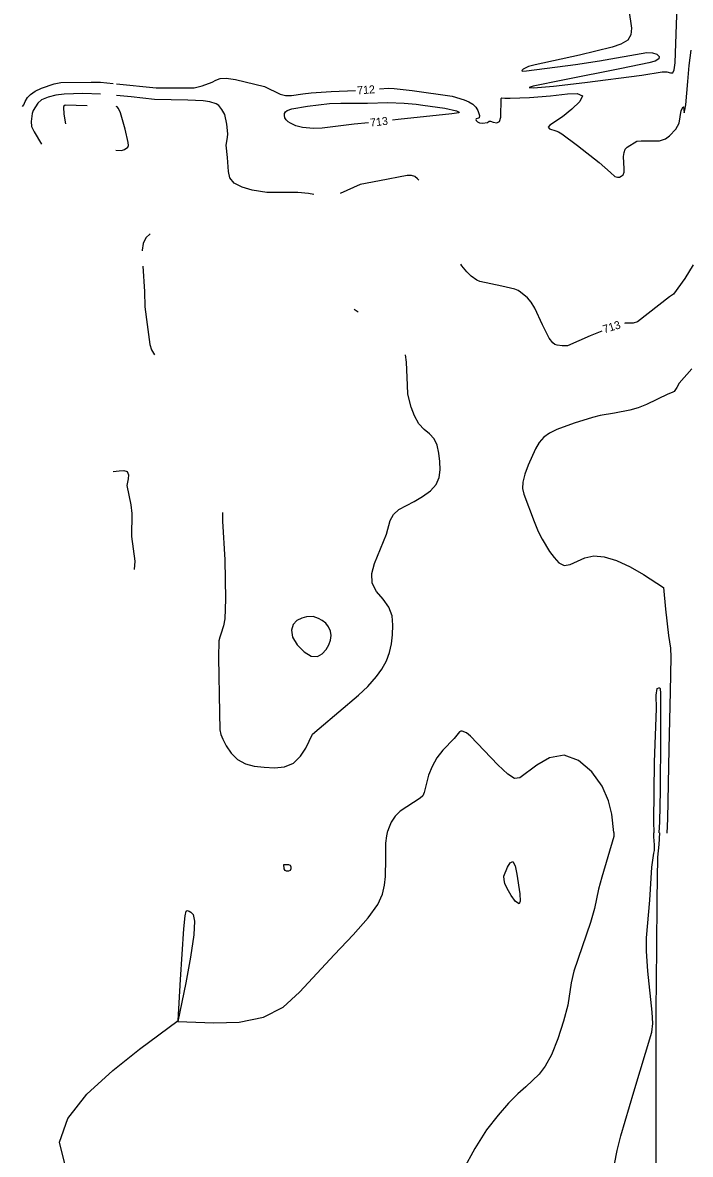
# Model space of a CAD drawing. Extents: x -468548933 to 3387700, y -306089263 to 1207014.
# Drawn here: x 1840205 to 1840538, y 537416 to 537981 of the extents above; entities that cross this region are included whole.
import ezdxf

# ---------------------------------------------------------------- set-up
doc = ezdxf.new("R2010")
doc.units = 0
doc.layers.add('DT_X_Contour_Minor', color=7, linetype='Continuous')
doc.layers.add('Level 19', color=7, linetype='Continuous')

msp = doc.modelspace()

# ---------------------------------------------------------------- linework, layer by layer
at = {"layer": 'DT_X_Contour_Minor'}
for points in [[(1840507.63, 537987.64), (1840508.91, 537978.47), (1840508.66, 537975.16), (1840507.03, 537972.57), (1840503.67, 537970.6), (1840499.31, 537969.11), (1840482.9, 537965.06), (1840460.77, 537960.16), (1840457.44, 537959.34), (1840454.78, 537957.98), (1840454.11, 537957.39), (1840454.34, 537957.09), (1840456.45, 537957.14), (1840481.01, 537960.37), (1840492.9, 537962.2), (1840516.67, 537966.34), (1840519.43, 537966.22), (1840521.6, 537965.49), (1840522.83, 537964.37), (1840522.65, 537963.15), (1840520.77, 537962.08), (1840517.52, 537961.14), (1840503.98, 537958.42), (1840474.59, 537952.57), (1840459.84, 537949.58), (1840457.79, 537948.88), (1840459.96, 537948.79), (1840469.92, 537949.59), (1840485.62, 537951.44), (1840514.13, 537954.97), (1840524.17, 537956.66), (1840526.6, 537956.67), (1840528.35, 537956.26), (1840529.53, 537956.26), (1840530.26, 537957.7), (1840530.69, 537961.18), (1840531.39, 537980.28), (1840532.25, 538003.02)], [(1840383.06, 537948.2), (1840387.5, 537948.52), (1840390.45, 537948.44), (1840399.41, 537947.42), (1840419.36, 537944.52), (1840425.33, 537942.72), (1840427.64, 537941.76), (1840429.68, 537940.52), (1840431.21, 537939), (1840432.23, 537937.39), (1840433.01, 537934.9), (1840432.83, 537933.79), (1840432.47, 537933.48), (1840431.33, 537933.21), (1840431.16, 537932.88), (1840431.38, 537932.35), (1840432.03, 537931.75), (1840433.09, 537931.27), (1840434.52, 537931.04), (1840437.05, 537931.35), (1840437.8, 537932.11), (1840438.46, 537932.05), (1840439.87, 537931.51), (1840441.6, 537931.14), (1840443, 537931.81), (1840443.63, 537934.06), (1840443.82, 537943.32), (1840444.1, 537943.77), (1840445.67, 537943.61), (1840448.29, 537943.49), (1840458, 537943.86), (1840468.44, 537944.64), (1840476.9, 537945.74), (1840481.86, 537945.91), (1840484.46, 537944.78), (1840483.14, 537941.86), (1840479.14, 537937.97), (1840474.42, 537934.29), (1840468.22, 537930.1), (1840467.32, 537929.07), (1840467.92, 537928.28), (1840471.09, 537927.16), (1840472.47, 537926.68), (1840474.19, 537925.68), (1840482.04, 537919.85), (1840492.84, 537911.32), (1840498.41, 537906.39), (1840500.67, 537904.32), (1840501.98, 537904.06), (1840502.89, 537904.14), (1840503.85, 537904.53), (1840504.7, 537905.3), (1840505.22, 537906.51), (1840505.31, 537908.17), (1840504.93, 537914.45), (1840505.21, 537916.4), (1840505.81, 537917.98), (1840506.74, 537919.06), (1840511.67, 537922.03), (1840513.73, 537922.24), (1840522.95, 537922.18), (1840525.84, 537923.19), (1840527.86, 537924.71), (1840531.16, 537928), (1840532.69, 537930.99), (1840533.69, 537937.37), (1840534.66, 537939.23), (1840534.91, 537939.14), (1840535.3, 537936.29), (1840535.62, 537937.48), (1840536.06, 537940.18), (1840537.09, 537951.85), (1840537.76, 537959.88), (1840538.71, 537967.56)], [(1840204.77, 537939.45), (1840205.42, 537940.16), (1840205.99, 537941.84), (1840207.28, 537943.81), (1840208.72, 537945.38), (1840211.01, 537947.03), (1840214.21, 537948.54), (1840220.53, 537950.67), (1840223.81, 537951.38), (1840239, 537951.58), (1840243.77, 537951.46), (1840250.04, 537950.84)], [(1840251.67, 537950.68), (1840271.53, 537948.73), (1840290.48, 537948.74), (1840294.41, 537949.67), (1840299.47, 537951.57), (1840301.36, 537952.62), (1840303.39, 537953.39), (1840306.45, 537953.53), (1840311.06, 537952.83), (1840325.55, 537949.33), (1840333.38, 537945.56), (1840336.13, 537944.96), (1840339.14, 537944.9), (1840344.76, 537945.67), (1840348.96, 537946.29), (1840358.89, 537946.91), (1840371.09, 537947.44)], [(1840243.72, 537945.49), (1840234.9, 537945.81), (1840225.6, 537945.62), (1840221.43, 537945.01), (1840217.63, 537944.02), (1840214.27, 537942.68), (1840212.41, 537941.03), (1840210, 537937.46), (1840209.49, 537935.87), (1840209.11, 537931.83), (1840209.27, 537929.39), (1840210.6, 537926.71), (1840214.23, 537920.5)], [(1840350.19, 537895.44), (1840347.67, 537895.92), (1840342.3, 537896.34), (1840331.9, 537896.37), (1840326.73, 537896.36), (1840319.51, 537897.61), (1840314.53, 537899.01), (1840310.44, 537901.04), (1840308.3, 537903.72), (1840307.6, 537906.9), (1840307.09, 537913.96), (1840306.46, 537920.09), (1840307.06, 537923.82), (1840307.3, 537925.67), (1840306.77, 537930.55), (1840305.84, 537935.43), (1840304.35, 537937.89), (1840302.79, 537939.91), (1840301.52, 537940.76), (1840298.38, 537941.72), (1840295.03, 537942.22), (1840287.31, 537942.56), (1840270.63, 537942.88), (1840258.95, 537944.16), (1840251.62, 537944.9)], [(1840236.99, 537939.78), (1840226.04, 537940.02), (1840225.35, 537939.54), (1840225.18, 537938.97), (1840225.45, 537935.61), (1840226.22, 537930.66)], [(1840251.4, 537917.52), (1840254.19, 537917.32), (1840255.71, 537917.83), (1840257.29, 537918.98), (1840257.63, 537919.84), (1840257.54, 537921.34), (1840256.02, 537928.03), (1840253.65, 537936.29), (1840252.7, 537938.42), (1840252, 537939.25), (1840251.58, 537939.37)], [(1840377.56, 537931.26), (1840370.4, 537930.57), (1840354.35, 537928.56), (1840350.17, 537928.4), (1840344.67, 537928.89), (1840341.23, 537929.8), (1840338.56, 537931), (1840337.39, 537931.75), (1840336.45, 537932.67), (1840335.82, 537933.75), (1840335.53, 537934.89), (1840335.64, 537935.93), (1840336.15, 537936.75), (1840336.98, 537937.36), (1840339.26, 537938.18), (1840347.02, 537939.5), (1840358.06, 537940.93), (1840363.7, 537941.1), (1840376.98, 537941.02), (1840387.23, 537941.33), (1840395.4, 537941.11), (1840401.44, 537940.55), (1840404.64, 537940.12), (1840415.74, 537938.6), (1840421.49, 537937.22), (1840422.86, 537936.63), (1840422.75, 537936.23), (1840419.22, 537935.71), (1840392.43, 537932.87), (1840389.49, 537932.54)], [(1840402.64, 537902.52), (1840402.12, 537903.27), (1840400.66, 537904.44), (1840399.11, 537904.93), (1840396.93, 537904.83), (1840383.07, 537902.25), (1840373.44, 537900.32), (1840370.03, 537898.86), (1840363.44, 537895.93)], [(1840268.56, 537875.67), (1840266.41, 537873.75), (1840265.08, 537870.98), (1840264.54, 537867.53), (1840264.54, 537867.17)], [(1840264.83, 537859.58), (1840265.67, 537846.9), (1840265.8, 537839.27), (1840266.99, 537830.43), (1840268.41, 537820.36), (1840269.24, 537817.8), (1840270.63, 537815.27)], [(1840494.13, 537827.17), (1840488.22, 537824.75), (1840477.02, 537819.81), (1840474.34, 537819.74), (1840471.72, 537820.09), (1840470.62, 537820.49), (1840469.63, 537821.2), (1840467.89, 537823.56), (1840464.48, 537830.35), (1840460.63, 537838.57), (1840458.86, 537841.55), (1840456.96, 537843.84), (1840453.52, 537846.6), (1840452.24, 537847.4), (1840450.68, 537848.05), (1840444.13, 537849.58), (1840433.1, 537851.92), (1840431.61, 537852.53), (1840428.83, 537854.65), (1840426.76, 537856.69), (1840424.15, 537859.78), (1840423.61, 537860.55)], [(1840539.73, 537860.26), (1840535.64, 537853.46), (1840529.87, 537845.64), (1840527.91, 537844.33), (1840511.97, 537831.85), (1840509.7, 537831.14), (1840505.84, 537831.05), (1840505.51, 537830.99)], [(1840372.32, 537836.67), (1840370.42, 537837.99)], [(1840304.62, 537736.49), (1840304.66, 537732.22), (1840305.77, 537712.86), (1840306.12, 537693.18), (1840305.74, 537683.31), (1840305.16, 537679.79), (1840303.74, 537675.62), (1840303.22, 537674.23), (1840302.88, 537672.37), (1840302.69, 537664.02), (1840303.06, 537636.33), (1840303.36, 537627.93), (1840303.83, 537625.61), (1840304.82, 537623.19), (1840306.52, 537619.88), (1840308.96, 537616.21), (1840312.15, 537613.01), (1840316.04, 537610.92), (1840320.52, 537609.76), (1840325.44, 537609.16), (1840330.61, 537608.91), (1840335.64, 537609.41), (1840340.11, 537611.24), (1840343.66, 537614.67), (1840346.27, 537618.78), (1840349.65, 537625.73), (1840352.96, 537628.51), (1840372.63, 537645.27), (1840377.31, 537649.47), (1840381.61, 537654.55), (1840384.22, 537658.24), (1840386.52, 537662.32), (1840388.1, 537666.52), (1840389.05, 537670.86), (1840389.58, 537675.39), (1840389.79, 537680.12), (1840389.33, 537684.84), (1840387.73, 537689.25), (1840384.82, 537693.2), (1840381.63, 537697.03), (1840379.47, 537701.21), (1840379.28, 537706.01), (1840380.56, 537711.01), (1840386.52, 537725.62), (1840388.4, 537732.43), (1840390.09, 537735.48), (1840392.78, 537737.91), (1840400.36, 537742.06), (1840404.6, 537744.5), (1840408.48, 537747.32), (1840411.39, 537750.51), (1840412.92, 537754.04), (1840413.35, 537757.85), (1840413.16, 537761.91), (1840412.71, 537766.11), (1840411.86, 537770.06), (1840410.36, 537773.35), (1840408.1, 537775.75), (1840405.41, 537777.92), (1840402.77, 537780.73), (1840400.56, 537784.72), (1840398.9, 537789.18), (1840397.25, 537795.69), (1840397.02, 537800.15), (1840396.49, 537811.62), (1840395.98, 537815.2)], [(1840539.14, 537808.26), (1840532.74, 537801.09), (1840531.61, 537798.96), (1840530.23, 537797.01), (1840529.24, 537796.4), (1840527.03, 537795.61), (1840516.46, 537790.46), (1840512.24, 537788.8), (1840508.09, 537787.58), (1840500.38, 537786.15), (1840493.28, 537784.94), (1840489.38, 537784), (1840480.28, 537781.11), (1840471.58, 537777.88), (1840468.01, 537776.18), (1840465.08, 537774.13), (1840462.82, 537771.52), (1840460.98, 537768.31), (1840457.37, 537760.07), (1840455.7, 537755.6), (1840454.62, 537751.63), (1840454.44, 537748.51), (1840455.09, 537745.61), (1840460.25, 537731.96), (1840462.32, 537727), (1840464.23, 537723.13), (1840468.04, 537717.05), (1840470.23, 537713.93), (1840472.67, 537711.27), (1840475.37, 537709.95), (1840478.34, 537710.5), (1840485.55, 537713.9), (1840490.06, 537714.76), (1840495.32, 537714.39), (1840501.45, 537712.56), (1840508.32, 537709.28), (1840514.96, 537705.44), (1840524.86, 537698.92), (1840525.95, 537688.22), (1840527.45, 537675.09), (1840528.46, 537668.61), (1840528.62, 537664.12), (1840528.26, 537646.99), (1840527.63, 537618.39), (1840526.9, 537583.35), (1840526.63, 537576.3)], [(1840250.06, 537756.91), (1840252.95, 537757.29), (1840255.33, 537757.47), (1840256.98, 537756.92), (1840257.6, 537755.35), (1840257.49, 537753.29), (1840256.81, 537750), (1840258.83, 537740.28), (1840259.31, 537735.98), (1840259.18, 537724.54), (1840260.85, 537712.19), (1840260.56, 537708.05), (1840260.53, 537707.95)], [(1840350, 537684.59), (1840346.61, 537684.28), (1840344.22, 537683.73), (1840341.82, 537682.55), (1840339.93, 537680.51), (1840339.02, 537677.69), (1840339.6, 537674.21), (1840341.93, 537670.35), (1840345.35, 537666.88), (1840348.96, 537664.73), (1840352.04, 537664.54), (1840354.49, 537665.87), (1840356.39, 537667.98), (1840357.76, 537670.28), (1840358.61, 537672.62), (1840358.87, 537674.96), (1840358.53, 537677.25), (1840357.63, 537679.38), (1840356.23, 537681.19), (1840354.44, 537682.56), (1840352.61, 537683.53), (1840350, 537684.59)], [(1840520.24, 537576.35), (1840520.16, 537582.03), (1840520.36, 537611.63), (1840521.37, 537638.53), (1840521.32, 537645.15), (1840521.79, 537648.54), (1840522.53, 537648.92), (1840523.1, 537648.79), (1840523.29, 537648.48), (1840523.47, 537646.05), (1840523.41, 537624.18), (1840523.18, 537597.61), (1840522.93, 537581.88), (1840522.59, 537576.33)], [(1840500.11, 537576.51), (1840499.04, 537585.69), (1840497.5, 537592.39), (1840494.36, 537599.79), (1840489.18, 537606.95), (1840482.53, 537612.54), (1840475.23, 537615.13), (1840468.05, 537613.86), (1840461.63, 537610.22), (1840453.18, 537603.83), (1840450.46, 537603.52), (1840447.09, 537605.7), (1840442.23, 537610.41), (1840428.49, 537624.76), (1840426.51, 537626.37), (1840424.36, 537627.21), (1840423.63, 537627.15), (1840423.07, 537626.85), (1840420.31, 537623.61), (1840414.65, 537617.76), (1840411.64, 537613.84), (1840409.29, 537609.53), (1840407.61, 537605.25), (1840405.9, 537598.6), (1840405.4, 537596.49), (1840404.68, 537594.93), (1840403.42, 537593.7), (1840393.45, 537587.26), (1840390.82, 537584.65), (1840388.83, 537581.65), (1840387.48, 537578.35), (1840387.26, 537577.41)], [(1840282.39, 537482.19), (1840300.36, 537481.4), (1840312.89, 537481.85), (1840325.09, 537484.22), (1840334.88, 537489.31), (1840343.11, 537496.72), (1840360.62, 537515.61), (1840369.85, 537525.35), (1840377.42, 537533.9), (1840382.15, 537540.51), (1840384.56, 537545.67), (1840385.58, 537550.17), (1840386.04, 537554.62), (1840386.19, 537563.34), (1840386.25, 537571.19), (1840386.64, 537574.84), (1840387.24, 537577.41)], [(1840500.11, 537576.51), (1840500.14, 537574.57), (1840494.07, 537554.25), (1840492.52, 537548.26), (1840490.39, 537538.59), (1840488.4, 537531.66), (1840480.08, 537507.25), (1840478.82, 537501.49), (1840477.07, 537490.35), (1840474.99, 537482.29), (1840472.14, 537473.41), (1840468.97, 537465.46), (1840465.87, 537459.75), (1840462.79, 537455.8), (1840456.08, 537449.54), (1840452.13, 537445.88), (1840447.56, 537441.28), (1840442.29, 537435.36), (1840436.53, 537427.9), (1840430.62, 537418.71), (1840424.91, 537407.94)], [(1840498.07, 537398.76), (1840501.79, 537417.56), (1840503.65, 537424.97), (1840510.04, 537447.04), (1840519.05, 537476.84), (1840519.57, 537481.12), (1840519.18, 537486.78), (1840517.17, 537507.28), (1840516.47, 537517.23), (1840516.45, 537523.93), (1840518.16, 537542.69), (1840519.16, 537559.3), (1840520.17, 537566.22), (1840520.47, 537567.49), (1840520.38, 537570.36), (1840520.15, 537574.48), (1840520.15, 537576.35)], [(1840522.9, 537576.33), (1840522.62, 537570.52), (1840521.85, 537564.16), (1840521.61, 537542.77), (1840521.34, 537518.77), (1840521.01, 537487.44), (1840521.01, 537461.74), (1840521.15, 537430.02), (1840521.01, 537411.34)], [(1840335.21, 537560.49), (1840337.59, 537560.57), (1840338.39, 537560.19), (1840338.8, 537559.41), (1840338.8, 537558.44), (1840338.37, 537557.62), (1840337.58, 537557.19), (1840336.65, 537557.19), (1840335.86, 537557.59), (1840335.41, 537558.33), (1840335.21, 537560.49)], [(1840445.19, 537554.81), (1840447.01, 537559.21), (1840448.31, 537561.45), (1840449.63, 537562.02), (1840450.75, 537559.87), (1840451.69, 537555.7), (1840453.18, 537545.88), (1840453.39, 537542.31), (1840452.74, 537540.88), (1840451.01, 537542.16), (1840448.79, 537545.15), (1840446.82, 537548.51), (1840445.71, 537551.13), (1840445.28, 537552.91), (1840445.19, 537554.81)], [(1840226.09, 537410.35), (1840223.19, 537421.8), (1840227.39, 537433.67), (1840236.91, 537445.75), (1840249.78, 537457.66), (1840263.14, 537468.24), (1840282.41, 537482.53), (1840283.61, 537503.04), (1840285.29, 537528.34), (1840285.95, 537534.85), (1840286.49, 537537.26), (1840286.95, 537537.59), (1840288.04, 537537.29), (1840288.88, 537536.75), (1840289.93, 537535.55), (1840290.65, 537532.32), (1840290.37, 537525.46), (1840288.7, 537514.26), (1840286.31, 537501.46), (1840282.39, 537482.19)]]:
    msp.add_lwpolyline(points, dxfattribs=at)

# ---------------------------------------------------------------- texts
at = {"layer": 'Level 19'}
for s, rotation, p in [('712', 4.1196, (1840372.01, 537945.4)), ('713', 6.4973, (1840378.56, 537929.28)), ('713', 17.2231, (1840495.3, 537826))]:
    msp.add_text(s, height=4, rotation=rotation, dxfattribs=at).set_placement(p)

doc.saveas('drawing.dxf')
